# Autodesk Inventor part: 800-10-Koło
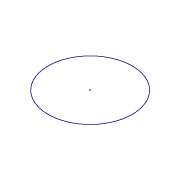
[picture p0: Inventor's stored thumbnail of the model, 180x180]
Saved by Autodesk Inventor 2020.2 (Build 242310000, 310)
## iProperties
Created: 2014-12
Part Number: 800-10-Koło
Material: Ogólny
Document SubType Name: Modeling
Designer: F.Stasiak
Density: 1 g/cm^3
Appearance: Domyślna
Catalog Web Link: www.expertbooks.pl
Manager: www.cadconsulting.pl
Company: Fabian Stasiak CAD Consulting
Author: F.Stasiak
Subject: Zbiór ćwiczeń. Autodesk Inventor 2020. Kurs Professional
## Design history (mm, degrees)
sketch "Szkic1"
  geometry: C1 r 304.8 at (0, 0) reference; 1 further point
  constraints: 1 centre point, 1 coincident, 2 other
